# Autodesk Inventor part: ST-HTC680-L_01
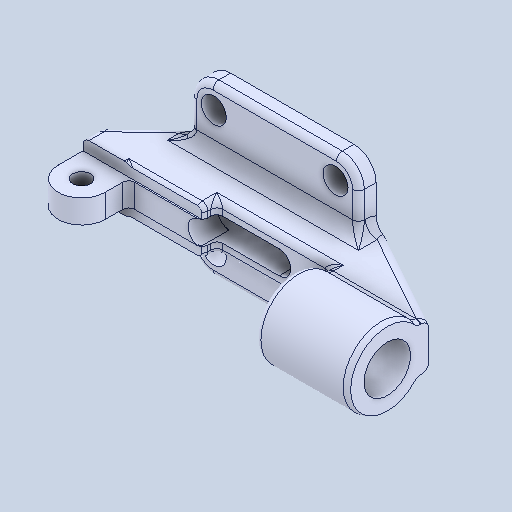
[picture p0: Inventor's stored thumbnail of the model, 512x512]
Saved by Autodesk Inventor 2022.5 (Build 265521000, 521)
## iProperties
Created: 2024-07
Part Number: ST-HTC680-L_01
Material: 一般
Document SubType Name: Modeling
Designer: ImaoCorp
Density: 1 g/cm^3
Appearance: 既定
Author: ImaoCorp
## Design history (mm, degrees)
feature "ST-HTC680-L_01"
node "ソリッド1"
